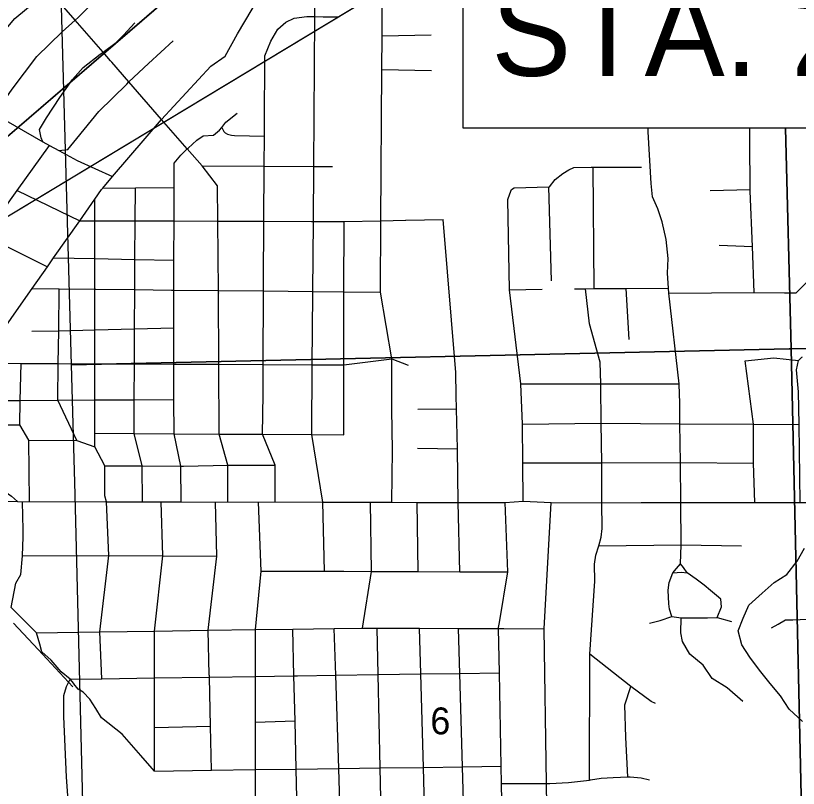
# Model space of a CAD drawing. Extents: x -37878.7 to -37844.7, y -19791.4 to -19769.4.
# Drawn here: x -37872.242 to -37871.021, y -19775.898 to -19774.693 of the extents above; entities that cross this region are included whole.
import ezdxf

# ---------------------------------------------------------------- set-up
doc = ezdxf.new("R2010")
doc.units = 0
for name, color, linetype in [('GM_X_City_Street', 7, 'Continuous'), ('GM_X_Minor_River', 7, 'Continuous'), ('GM_X_Rail_Line', 7, 'Continuous'), ('GM_X_Section', 7, 'Continuous'), ('GM_X_Section_Text', 7, 'Continuous'), ('GM_X_State_Route', 7, 'Continuous'), ('TX_P_1', 7, 'Continuous')]:
    doc.layers.add(name, color=color, linetype=linetype)

msp = doc.modelspace()

# ---------------------------------------------------------------- linework, layer by layer
at = {"layer": 'GM_X_City_Street'}
for points in [[(-37872.3287, -19774.8159), (-37872.3022, -19774.7677), (-37872.2433, -19774.6974), (-37872.2097, -19774.6698), (-37872.1882, -19774.6547), (-37872.1847, -19774.6522), (-37872.1692, -19774.6318), (-37872.1649, -19774.615), (-37872.1639, -19774.5876), (-37872.1628, -19774.5477)], [(-37872.092, -19774.7656), (-37872.0938, -19774.7635), (-37872.1055, -19774.7499), (-37872.1489, -19774.7001), (-37872.1882, -19774.6547), (-37872.2195, -19774.6187)], [(-37871.6552, -19775.4518), (-37871.6539, -19775.3706), (-37871.6549, -19775.3071), (-37871.6549, -19775.2283), (-37871.6728, -19775.1244), (-37871.6721, -19775.0128), (-37871.6706, -19774.7769), (-37871.6703, -19774.7245), (-37871.67, -19774.6758), (-37871.6698, -19774.633)], [(-37871.7783, -19775.1244), (-37871.7783, -19775.1232), (-37871.7775, -19775.0138), (-37871.7769, -19774.9281), (-37871.7753, -19774.6945), (-37871.7749, -19774.6363)], [(-37872.2751, -19774.8469), (-37872.2473, -19774.8077), (-37872.209, -19774.7565), (-37872.1695, -19774.7182), (-37872.1489, -19774.7001), (-37872.1442, -19774.696), (-37872.1248, -19774.6762), (-37872.1159, -19774.6604), (-37872.1159, -19774.6604)], [(-37871.855, -19775.1086), (-37871.8545, -19775.0136), (-37871.8541, -19774.9276), (-37871.8539, -19774.881), (-37871.8538, -19774.8627), (-37871.8532, -19774.7556), (-37871.8437, -19774.7329), (-37871.8329, -19774.7143), (-37871.8203, -19774.7033), (-37871.8072, -19774.6968), (-37871.7876, -19774.6943), (-37871.7753, -19774.6945), (-37871.7622, -19774.6947), (-37871.7384, -19774.6947)], [(-37872.1993, -19774.8896), (-37872.2019, -19774.8838), (-37872.2047, -19774.8706), (-37872.194, -19774.8524), (-37872.1732, -19774.8208), (-37872.153, -19774.7927), (-37872.1367, -19774.7739), (-37872.1098, -19774.7531), (-37872.1055, -19774.7499), (-37872.0851, -19774.7347), (-37872.0734, -19774.7236), (-37872.0559, -19774.704)], [(-37871.6703, -19774.7245), (-37871.5939, -19774.7229)], [(-37872.1745, -19774.9033), (-37872.1606, -19774.9019), (-37872.1465, -19774.8847), (-37872.1121, -19774.8424), (-37872.0686, -19774.7997), (-37872.0651, -19774.7965), (-37872.0345, -19774.7677), (-37871.996, -19774.7324)], [(-37872.0144, -19774.8549), (-37872.0651, -19774.7965), (-37872.092, -19774.7656)], [(-37871.6706, -19774.7769), (-37871.593, -19774.7784)], [(-37872.3629, -19774.7981), (-37872.3287, -19774.8159), (-37872.2751, -19774.8469), (-37872.1993, -19774.8896), (-37872.1889, -19774.8954), (-37872.1745, -19774.9033), (-37872.1459, -19774.9188), (-37872.0907, -19774.944)], [(-37871.9945, -19774.9434), (-37871.9944, -19774.9233), (-37871.9843, -19774.9108), (-37871.9741, -19774.9008), (-37871.973, -19774.8997), (-37871.959, -19774.887), (-37871.9494, -19774.8802), (-37871.9335, -19774.8796), (-37871.924, -19774.8716), (-37871.9204, -19774.8673), (-37871.9138, -19774.8591), (-37871.8962, -19774.8451)], [(-37871.911, -19775.451), (-37871.9108, -19775.3943), (-37871.9245, -19775.3455), (-37871.9249, -19775.2368), (-37871.9253, -19775.1252), (-37871.9253, -19775.1256), (-37871.9253, -19775.1216), (-37871.9264, -19775.0134), (-37871.9269, -19774.9585), (-37871.951, -19774.9271), (-37871.9741, -19774.9008), (-37872.0144, -19774.8549)], [(-37871.9204, -19774.8673), (-37871.9173, -19774.8735), (-37871.9151, -19774.876), (-37871.9115, -19774.8778), (-37871.9052, -19774.8796), (-37871.9006, -19774.8801), (-37871.8539, -19774.881)], [(-37871.2068, -19775.268), (-37871.2069, -19775.2672), (-37871.2232, -19775.1258), (-37871.2236, -19775.1179), (-37871.2249, -19775.0947), (-37871.224, -19775.0715), (-37871.2272, -19775.042), (-37871.2333, -19775.0148), (-37871.2404, -19774.9941), (-37871.2485, -19774.9754), (-37871.2506, -19774.9549), (-37871.2553, -19774.8742), (-37871.2553, -19774.8684)], [(-37871.0965, -19774.8884), (-37871.0966, -19774.8684)], [(-37871.0898, -19775.1248), (-37871.0927, -19775.0528), (-37871.096, -19774.9666), (-37871.096, -19774.9643), (-37871.0965, -19774.8886), (-37871.0965, -19774.8884)], [(-37872.2863, -19775.0307), (-37872.2395, -19774.9658), (-37872.1889, -19774.8954)], [(-37871.951, -19774.9271), (-37871.8541, -19774.9276), (-37871.7769, -19774.9281), (-37871.7476, -19774.9282)], [(-37871.4501, -19775.45), (-37871.4506, -19775.3906), (-37871.4511, -19775.3302), (-37871.4537, -19775.2672), (-37871.4716, -19775.1207), (-37871.4739, -19774.9795), (-37871.4711, -19774.9707), (-37871.4682, -19774.9644), (-37871.4642, -19774.9617), (-37871.41, -19774.9601), (-37871.4089, -19774.9601), (-37871.4005, -19774.9484), (-37871.3883, -19774.9393), (-37871.3788, -19774.9336), (-37871.3711, -19774.9301), (-37871.3439, -19774.9293), (-37871.3409, -19774.9293), (-37871.2658, -19774.9292)], [(-37871.3394, -19775.1187), (-37871.3409, -19774.9293)], [(-37871.9838, -19775.4513), (-37871.9843, -19775.3956), (-37871.9947, -19775.3451), (-37871.9949, -19775.2919), (-37871.995, -19775.2365), (-37871.9952, -19775.18), (-37871.9952, -19775.1716), (-37871.995, -19775.1209), (-37871.9949, -19775.0744), (-37871.9947, -19775.0132), (-37871.9946, -19774.9609), (-37871.9945, -19774.9444), (-37871.9945, -19774.9434)], [(-37872.1059, -19774.9619), (-37872.0551, -19774.9614), (-37871.9946, -19774.9609)], [(-37872.0439, -19775.4513), (-37872.0444, -19775.3951), (-37872.0572, -19775.3447), (-37872.0569, -19775.2922), (-37872.0566, -19775.2362), (-37872.0563, -19775.1815), (-37872.056, -19775.1202), (-37872.0557, -19775.0732), (-37872.0553, -19775.013), (-37872.0551, -19774.9614)], [(-37871.406, -19775.1066), (-37871.41, -19774.9601)], [(-37872.2395, -19774.9658), (-37872.142, -19775.0128)], [(-37871.1586, -19774.9655), (-37871.096, -19774.9643)], [(-37871.0426, -19775.1251), (-37871.0242, -19775.1252), (-37870.9403, -19775.041), (-37870.9391, -19775.0399), (-37870.8559, -19774.9652), (-37870.8558, -19774.9651)], [(-37872.1004, -19775.451), (-37872.103, -19775.4421), (-37872.1027, -19775.3953), (-37872.1182, -19775.3656), (-37872.1182, -19775.3443), (-37872.1182, -19775.2924), (-37872.1182, -19775.2359), (-37872.1182, -19775.183), (-37872.1183, -19775.1196), (-37872.1183, -19775.0719), (-37872.1183, -19775.0129), (-37872.1183, -19774.9791)], [(-37871.6726, -19775.0128), (-37871.6721, -19775.0128), (-37871.6336, -19775.0121), (-37871.6335, -19775.0121)], [(-37871.6335, -19775.0121), (-37871.5749, -19775.011)], [(-37871.5545, -19775.2853), (-37871.5551, -19775.2493), (-37871.5749, -19775.011)], [(-37872.142, -19775.0128), (-37872.1183, -19775.0129), (-37872.0553, -19775.013), (-37872.0051, -19775.0132), (-37872.0051, -19775.0132)], [(-37872.0051, -19775.0132), (-37871.9947, -19775.0132), (-37871.9269, -19775.0134)], [(-37871.9269, -19775.0134), (-37871.9264, -19775.0134), (-37871.8545, -19775.0136), (-37871.7803, -19775.0138), (-37871.7802, -19775.0138)], [(-37871.7802, -19775.0138), (-37871.7775, -19775.0138), (-37871.7295, -19775.0139), (-37871.6727, -19775.0128), (-37871.6726, -19775.0128)], [(-37871.7299, -19775.2352), (-37871.7297, -19775.1238), (-37871.7295, -19775.0139)], [(-37872.2902, -19775.0361), (-37872.1923, -19775.0845)], [(-37871.1443, -19775.0509), (-37871.0927, -19775.0528)], [(-37872.1826, -19775.0707), (-37872.1183, -19775.0719), (-37872.0557, -19775.0732), (-37871.9949, -19775.0744)], [(-37871.8372, -19775.4513), (-37871.8369, -19775.394), (-37871.8567, -19775.3459), (-37871.8558, -19775.284), (-37871.8556, -19775.2371), (-37871.8551, -19775.1224), (-37871.855, -19775.1102), (-37871.855, -19775.1086)], [(-37872.2162, -19775.1185), (-37872.1739, -19775.119), (-37872.1183, -19775.1196), (-37872.1174, -19775.1196), (-37872.1169, -19775.1196)], [(-37872.1466, -19775.3554), (-37872.1759, -19775.2927), (-37872.1753, -19775.2356), (-37872.1747, -19775.1843), (-37872.1739, -19775.119)], [(-37872.1169, -19775.1196), (-37872.056, -19775.1202), (-37871.9988, -19775.1209), (-37871.9978, -19775.1209)], [(-37871.9978, -19775.1209), (-37871.995, -19775.1209), (-37871.9253, -19775.1216), (-37871.8551, -19775.1224), (-37871.7783, -19775.1232), (-37871.7297, -19775.1238), (-37871.6728, -19775.1244)], [(-37871.4716, -19775.1207), (-37871.4208, -19775.1195)], [(-37871.3701, -19775.1189), (-37871.3528, -19775.1188), (-37871.3394, -19775.1187), (-37871.2895, -19775.1184), (-37871.2236, -19775.1179)], [(-37871.3292, -19775.2691), (-37871.3293, -19775.2672), (-37871.3303, -19775.2336), (-37871.3468, -19775.1736), (-37871.3528, -19775.1188)], [(-37871.285, -19775.1981), (-37871.2895, -19775.1184)], [(-37871.7629, -19775.4518), (-37871.7798, -19775.3464), (-37871.7791, -19775.2375), (-37871.7783, -19775.1271), (-37871.7783, -19775.1244)], [(-37871.2232, -19775.1258), (-37871.0898, -19775.1248), (-37871.0426, -19775.1251)], [(-37872.2165, -19775.1853), (-37872.1747, -19775.1843), (-37872.1182, -19775.183), (-37872.0563, -19775.1815), (-37871.9952, -19775.18)], [(-37872.2979, -19775.235), (-37872.2331, -19775.2353), (-37872.1753, -19775.2356), (-37872.1182, -19775.2359), (-37872.0566, -19775.2362), (-37871.995, -19775.2365), (-37871.9249, -19775.2368), (-37871.8556, -19775.2371), (-37871.7791, -19775.2375), (-37871.7299, -19775.2377), (-37871.6549, -19775.2283), (-37871.6297, -19775.2382)], [(-37871.1041, -19775.2313), (-37871.0591, -19775.2269), (-37871.0207, -19775.2306), (-37871.0155, -19775.2258), (-37871.0145, -19775.2249)], [(-37871.0887, -19775.4521), (-37871.0908, -19775.3911), (-37871.0908, -19775.3302), (-37871.1041, -19775.2313)], [(-37871.0183, -19775.4521), (-37871.0199, -19775.3307), (-37871.0209, -19775.2798), (-37871.0237, -19775.2452), (-37871.0207, -19775.2306)], [(-37872.2205, -19775.4506), (-37872.2212, -19775.3549), (-37872.2356, -19775.331), (-37872.2346, -19775.293), (-37872.2331, -19775.2353)], [(-37871.7301, -19775.3466), (-37871.7299, -19775.2377), (-37871.7299, -19775.2357), (-37871.7299, -19775.2352)], [(-37871.4537, -19775.2672), (-37871.3293, -19775.2672), (-37871.2069, -19775.2672)], [(-37871.2042, -19775.4521), (-37871.2048, -19775.3901), (-37871.2058, -19775.3297), (-37871.2058, -19775.2966), (-37871.2068, -19775.268)], [(-37872.3238, -19775.2719), (-37872.3008, -19775.2922), (-37872.292, -19775.2924), (-37872.2663, -19775.2931), (-37872.2346, -19775.293), (-37872.1759, -19775.2927), (-37872.1182, -19775.2924), (-37872.0569, -19775.2922), (-37871.9949, -19775.2919)], [(-37871.3277, -19775.4526), (-37871.3277, -19775.3906), (-37871.3287, -19775.3286), (-37871.3292, -19775.2691)], [(-37871.5515, -19775.4523), (-37871.5525, -19775.3685), (-37871.5541, -19775.306), (-37871.5545, -19775.2853)], [(-37871.6145, -19775.3066), (-37871.5541, -19775.306)], [(-37872.2838, -19775.3192), (-37872.281, -19775.3233), (-37872.2739, -19775.3314), (-37872.2356, -19775.331)], [(-37871.4511, -19775.3302), (-37871.3287, -19775.3286), (-37871.2058, -19775.3297), (-37871.0908, -19775.3302), (-37871.0199, -19775.3307)], [(-37872.1182, -19775.3443), (-37872.0572, -19775.3447), (-37871.9947, -19775.3451), (-37871.9245, -19775.3455), (-37871.8567, -19775.3459), (-37871.7798, -19775.3464), (-37871.7301, -19775.3466)], [(-37872.3701, -19775.3595), (-37872.3097, -19775.3999), (-37872.2481, -19775.4426), (-37872.2391, -19775.4506)], [(-37872.2212, -19775.3549), (-37872.1466, -19775.3554), (-37872.1182, -19775.3656)], [(-37871.6151, -19775.3676), (-37871.5525, -19775.3685)], [(-37871.4506, -19775.3906), (-37871.3277, -19775.3906), (-37871.2048, -19775.3901), (-37871.0908, -19775.3911)], [(-37872.1027, -19775.3953), (-37872.0444, -19775.3951), (-37871.9843, -19775.3956), (-37871.9801, -19775.3955)], [(-37871.9801, -19775.3955), (-37871.9108, -19775.3943), (-37871.8369, -19775.394)], [(-37872.2491, -19775.6159), (-37872.2414, -19775.578), (-37872.2338, -19775.5647), (-37872.231, -19775.5357), (-37872.2301, -19775.5057), (-37872.2301, -19775.4949), (-37872.231, -19775.451)], [(-37872.1075, -19775.7272), (-37872.1104, -19775.654), (-37872.0967, -19775.5351), (-37872.1004, -19775.451)], [(-37872.0254, -19775.7364), (-37872.0254, -19775.7259), (-37872.0254, -19775.6528), (-37872.0121, -19775.5353), (-37872.0148, -19775.451)], [(-37871.8635, -19775.4515), (-37871.8595, -19775.5592), (-37871.868, -19775.6505), (-37871.868, -19775.7236), (-37871.868, -19775.795), (-37871.868, -19775.8689), (-37871.868, -19775.9359), (-37871.868, -19776.0094), (-37871.8859, -19776.0358), (-37871.9087, -19776.0695), (-37871.9432, -19776.1035)], [(-37871.9398, -19775.7209), (-37871.9414, -19775.6516), (-37871.9278, -19775.5361), (-37871.9299, -19775.4515)], [(-37871.76, -19775.5595), (-37871.7629, -19775.4518)], [(-37871.7009, -19775.6481), (-37871.687, -19775.5598), (-37871.6885, -19775.4518)], [(-37871.4871, -19775.6392), (-37871.474, -19775.5603), (-37871.4782, -19775.4521)], [(-37871.4122, -19775.9946), (-37871.4138, -19775.8907), (-37871.4176, -19775.6493), (-37871.4065, -19775.4521)], [(-37871.2184, -19775.6301), (-37871.2221, -19775.6186), (-37871.2231, -19775.6102), (-37871.2242, -19775.5892), (-37871.2226, -19775.5771), (-37871.2168, -19775.5619), (-37871.2111, -19775.555), (-37871.2048, -19775.5477), (-37871.2037, -19775.5183), (-37871.2042, -19775.4521)], [(-37871.614, -19775.5598), (-37871.6158, -19775.4523)], [(-37871.5491, -19775.5605), (-37871.5515, -19775.4523)], [(-37871.3469, -19775.8852), (-37871.3463, -19775.689), (-37871.3382, -19775.575), (-37871.3392, -19775.5482), (-37871.3371, -19775.5345), (-37871.3324, -19775.5198), (-37871.3287, -19775.5062), (-37871.3272, -19775.493), (-37871.3277, -19775.4526)], [(-37871.3324, -19775.5198), (-37871.2037, -19775.5183), (-37871.1097, -19775.5198)], [(-37872.231, -19775.5357), (-37872.0967, -19775.5351), (-37872.0121, -19775.5353), (-37871.9278, -19775.5361)], [(-37871.1475, -19775.6317), (-37871.1407, -19775.6149), (-37871.1417, -19775.6028), (-37871.1486, -19775.5971), (-37871.158, -19775.5897), (-37871.168, -19775.5813), (-37871.1806, -19775.5718), (-37871.1943, -19775.5619), (-37871.2, -19775.5535), (-37871.2048, -19775.5477)], [(-37871.8595, -19775.5592), (-37871.76, -19775.5595), (-37871.7302, -19775.5596), (-37871.687, -19775.5598), (-37871.614, -19775.5598), (-37871.5491, -19775.5605), (-37871.474, -19775.5603)], [(-37871.2168, -19775.5619), (-37871.2032, -19775.5608), (-37871.1943, -19775.5619)], [(-37872.1513, -19775.7344), (-37872.1567, -19775.7279), (-37872.1709, -19775.7161), (-37872.1867, -19775.6981), (-37872.2009, -19775.6854), (-37872.204, -19775.6734), (-37872.2095, -19775.6554), (-37872.2163, -19775.6488), (-37872.2325, -19775.6323), (-37872.2491, -19775.6159)], [(-37871.2531, -19775.6407), (-37871.2363, -19775.6365), (-37871.2184, -19775.6301), (-37871.2037, -19775.6322), (-37871.1822, -19775.6322), (-37871.1627, -19775.6322), (-37871.1475, -19775.6317), (-37871.1254, -19775.638)], [(-37871.1078, -19775.7624), (-37871.1321, -19775.7411), (-37871.1556, -19775.7266), (-37871.1695, -19775.7058), (-37871.1905, -19775.6889), (-37871.2016, -19775.669), (-37871.2042, -19775.6554), (-37871.2037, -19775.6322)], [(-37871.0629, -19775.6477), (-37871.0524, -19775.6422), (-37871.0411, -19775.6355), (-37871.0298, -19775.6353), (-37870.9952, -19775.6338)], [(-37871.4799, -19776.1129), (-37871.484, -19775.8903), (-37871.4845, -19775.8637), (-37871.4872, -19775.7179), (-37871.4885, -19775.649), (-37871.4885, -19775.6473), (-37871.4871, -19775.6392)], [(-37872.2095, -19775.6554), (-37872.1104, -19775.654), (-37872.0254, -19775.6528), (-37871.9414, -19775.6516), (-37871.868, -19775.6505), (-37871.8096, -19775.6497), (-37871.7448, -19775.6487), (-37871.7009, -19775.6481), (-37871.6778, -19775.6482), (-37871.6119, -19775.6485), (-37871.5512, -19775.6487), (-37871.4958, -19775.649), (-37871.4885, -19775.649), (-37871.4806, -19775.649)], [(-37871.8007, -19776.0091), (-37871.8025, -19775.9354), (-37871.8042, -19775.868), (-37871.8061, -19775.793), (-37871.8078, -19775.7227), (-37871.8096, -19775.6497)], [(-37871.733, -19776.0239), (-37871.733, -19776.0239), (-37871.7334, -19776.0088), (-37871.7379, -19775.8671), (-37871.7425, -19775.7217), (-37871.7448, -19775.6487)], [(-37871.6699, -19776.0234), (-37871.6702, -19776.0085), (-37871.6732, -19775.8662), (-37871.6763, -19775.7207), (-37871.6778, -19775.6482)], [(-37871.6001, -19776.0663), (-37871.6018, -19776.0082), (-37871.6058, -19775.8653), (-37871.6099, -19775.7197), (-37871.6119, -19775.6485)], [(-37871.5408, -19776.008), (-37871.5408, -19776.008), (-37871.545, -19775.8645), (-37871.5492, -19775.7188), (-37871.5512, -19775.6487)], [(-37871.4806, -19775.649), (-37871.4176, -19775.6493)], [(-37871.2439, -19775.7657), (-37871.2504, -19775.7625), (-37871.2824, -19775.7393), (-37871.3463, -19775.689)], [(-37871.8023, -19775.7226), (-37871.8023, -19775.7226), (-37871.7425, -19775.7217), (-37871.6763, -19775.7207), (-37871.6099, -19775.7197), (-37871.5492, -19775.7188), (-37871.4872, -19775.7179)], [(-37872.1584, -19775.9385), (-37872.1627, -19775.8806), (-37872.1667, -19775.7862), (-37872.1668, -19775.7532), (-37872.1624, -19775.7393), (-37872.1567, -19775.7279)], [(-37872.1567, -19775.7279), (-37872.1075, -19775.7272), (-37872.0254, -19775.7259), (-37871.9397, -19775.7246), (-37871.868, -19775.7236), (-37871.8078, -19775.7227), (-37871.8023, -19775.7226)], [(-37871.9363, -19775.8698), (-37871.9379, -19775.801), (-37871.9397, -19775.7246), (-37871.9397, -19775.7224), (-37871.9398, -19775.7209)], [(-37872.0255, -19775.871), (-37872.0465, -19775.8469), (-37872.0758, -19775.8135), (-37872.1078, -19775.7881), (-37872.1167, -19775.7736), (-37872.126, -19775.7592), (-37872.1367, -19775.7478), (-37872.1444, -19775.7432), (-37872.1509, -19775.7349), (-37872.1513, -19775.7344)], [(-37872.0255, -19775.871), (-37872.0254, -19775.8031), (-37872.0254, -19775.7392), (-37872.0254, -19775.7364)], [(-37871.2867, -19775.8803), (-37871.2901, -19775.8188), (-37871.2916, -19775.7676), (-37871.2824, -19775.7393)], [(-37871.868, -19775.795), (-37871.8061, -19775.793)], [(-37872.0254, -19775.8031), (-37871.9379, -19775.801)], [(-37872.0255, -19775.871), (-37871.9363, -19775.8698), (-37871.868, -19775.8689), (-37871.8042, -19775.868), (-37871.7379, -19775.8671), (-37871.6732, -19775.8662), (-37871.6058, -19775.8653), (-37871.545, -19775.8645), (-37871.4845, -19775.8637)], [(-37871.484, -19775.8903), (-37871.4138, -19775.8907), (-37871.4135, -19775.8907)], [(-37871.4135, -19775.8907), (-37871.4088, -19775.8907), (-37871.3797, -19775.8887), (-37871.3469, -19775.8852), (-37871.3453, -19775.885), (-37871.3287, -19775.8823), (-37871.3098, -19775.8813), (-37871.2867, -19775.8803), (-37871.2833, -19775.8801), (-37871.2662, -19775.8819), (-37871.2533, -19775.8849)]]:
    msp.add_lwpolyline(points, dxfattribs=at)
at = {"layer": 'GM_X_Minor_River'}
msp.add_lwpolyline([(-37871.0147, -19775.7936), (-37871.0351, -19775.7745), (-37871.0486, -19775.754), (-37871.0647, -19775.7345), (-37871.0816, -19775.7139), (-37871.0966, -19775.6937), (-37871.109, -19775.6743), (-37871.115, -19775.6526), (-37871.1069, -19775.6326), (-37871.098, -19775.6125), (-37871.0775, -19775.5936), (-37871.0585, -19775.577), (-37871.0391, -19775.5645), (-37871.023, -19775.5437), (-37871.0116, -19775.5236)], dxfattribs=at)
at = {"layer": 'GM_X_Rail_Line'}
msp.add_lwpolyline([(-37872.1526, -19775.7399), (-37872.2067, -19775.6817), (-37872.2453, -19775.6407)], dxfattribs=at)
at = {"layer": 'GM_X_Section'}
for points in [[(-37871.041, -19774.8684), (-37871.0324, -19775.2124), (-37871.0355, -19775.2124), (-37872.1545, -19775.2374), (-37872.1703, -19774.6795), (-37872.1869, -19774.0898)], [(-37869.9174, -19774.8684), (-37869.91, -19775.19), (-37871.0324, -19775.2124), (-37871.041, -19774.8684)]]:
    msp.add_lwpolyline(points, dxfattribs=at)
for points in [[(-37869.91, -19775.19), (-37869.8966, -19775.75), (-37869.8839, -19776.3111), (-37871.0074, -19776.3279), (-37871.0324, -19775.2124)], [(-37871.0324, -19775.2124), (-37871.0074, -19776.3279), (-37872.1261, -19776.3478), (-37872.1311, -19776.15), (-37872.1488, -19775.4398), (-37872.1545, -19775.2374), (-37871.0355, -19775.2124)]]:
    msp.add_lwpolyline(points, close=True, dxfattribs=at)
at = {"layer": 'GM_X_State_Route'}
for points in [[(-37872.3345, -19775.2871), (-37872.3238, -19775.2719), (-37872.2979, -19775.235), (-37872.2442, -19775.1584), (-37872.2162, -19775.1185), (-37872.1923, -19775.0845), (-37872.1826, -19775.0707), (-37872.142, -19775.0128), (-37872.1183, -19774.9791), (-37872.1077, -19774.9639), (-37872.1059, -19774.9619), (-37872.0907, -19774.944), (-37872.0144, -19774.8549), (-37871.9375, -19774.7717), (-37871.9152, -19774.7564), (-37871.8956, -19774.7213), (-37871.8486, -19774.6411), (-37871.8448, -19774.6347), (-37871.8377, -19774.6229), (-37871.8287, -19774.5987), (-37871.8286, -19774.5983)], [(-37872.4121, -19775.4498), (-37872.3742, -19775.4504), (-37872.2391, -19775.4506), (-37872.231, -19775.451), (-37872.2205, -19775.4506), (-37872.1004, -19775.451), (-37872.0439, -19775.4513), (-37872.0148, -19775.451), (-37871.9838, -19775.4513), (-37871.9299, -19775.4515), (-37871.911, -19775.451), (-37871.8635, -19775.4515), (-37871.8372, -19775.4513), (-37871.7629, -19775.4518), (-37871.6885, -19775.4518), (-37871.6552, -19775.4518), (-37871.6158, -19775.4523), (-37871.5515, -19775.4523), (-37871.4782, -19775.4521)], [(-37871.4782, -19775.4521), (-37871.4501, -19775.45), (-37871.4065, -19775.4521), (-37871.3277, -19775.4526), (-37871.2662, -19775.4521), (-37871.2042, -19775.4521), (-37871.0887, -19775.4521), (-37871.0183, -19775.4521), (-37870.9971, -19775.4522)]]:
    msp.add_lwpolyline(points, dxfattribs=at)
at = {"layer": 'TX_P_1'}
for p, q in [((-37872.7415, -19775.2998), (-37871.544, -19774.2693)), ((-37871.544, -19774.8684), (-37871.544, -19774.2693)), ((-37872.7415, -19775.2998), (-37871.544, -19774.5775)), ((-37869.5652, -19774.8684), (-37871.544, -19774.8684))]:
    msp.add_line(p, q, dxfattribs=at)
msp.add_lwpolyline([(-37872.7415, -19775.2998), (-37871.544, -19774.2693), (-37871.544, -19774.5775)], close=True, dxfattribs=at)

# ---------------------------------------------------------------- texts
at = {"layer": 'GM_X_Section_Text'}
msp.add_text('6', height=0.0419, rotation=0, dxfattribs=at).set_placement((-37871.595, -19775.8138))
at = {"layer": 'TX_P_1'}
msp.add_text('STA. 25+00.00', height=0.14, rotation=360, dxfattribs=at).set_placement((-37871.5, -19774.7869))

doc.saveas('drawing.dxf')
